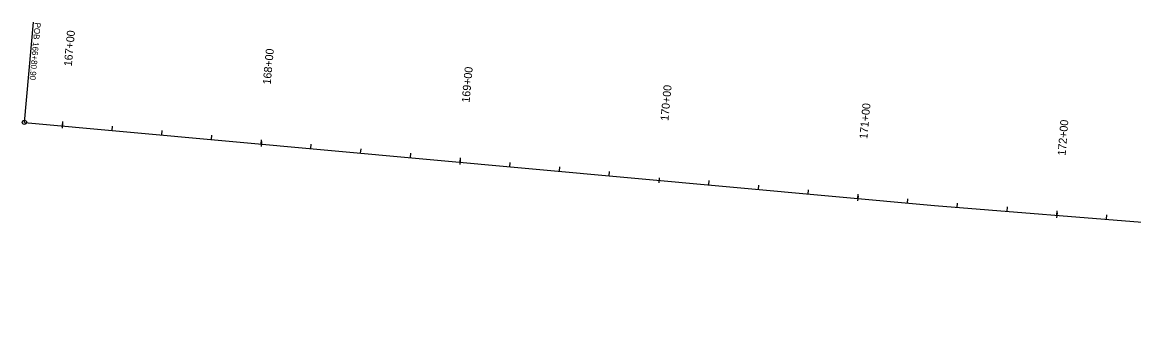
# Model space of a CAD drawing. Extents: x 20500393 to 20505339, y 7953466 to 7954298.
# Drawn here: x 20500393 to 20500950, y 7953909 to 7954061 of the extents above; entities that cross this region are included whole.
import ezdxf

# ---------------------------------------------------------------- set-up
doc = ezdxf.new("R2010")
doc.units = 0
for name, color, linetype in [('_CIVIL_CONSTRUCTION', 7, 'Continuous'), ('TextAlignment', 7, 'Continuous'), ('TextAlignmentLrg', 7, 'Continuous'), ('TextAlignmentSml', 7, 'Continuous')]:
    doc.layers.add(name, color=color, linetype=linetype)

msp = doc.modelspace()

# ---------------------------------------------------------------- linework, layer by layer
at = {"layer": '_CIVIL_CONSTRUCTION'}
for p, q in [((20500394.39, 7954010.65), (20500850.16, 7953968.94)), ((20500394.39, 7954010.65), (20500850.16, 7953968.94)), ((20500850.16, 7953968.94), (20501601.96, 7953909.2)), ((20500850.16, 7953968.94), (20501601.96, 7953909.2))]:
    msp.add_line(p, q, dxfattribs=at)
at = {"layer": 'TextAlignment'}
for p in [(20500394.39, 7954010.65), (20500398.98, 7954060.84)]:
    msp.add_line(p, (20500398.98, 7954060.84), dxfattribs=at)
msp.add_circle((20500394.39, 7954010.65), 1.07, dxfattribs=at)
at = {"layer": 'TextAlignmentLrg'}
for p, q in [((20500413.4, 7954008.91), (20500413.6, 7954011.09)), ((20500512.99, 7953999.8), (20500513.19, 7954001.97)), ((20500612.57, 7953990.69), (20500612.77, 7953992.86)), ((20500712.27, 7953982.79), (20500712.04, 7953980.35)), ((20500811.74, 7953972.46), (20500811.94, 7953974.64)), ((20500911.39, 7953964.08), (20500911.56, 7953966.26))]:
    msp.add_line(p, q, dxfattribs=at)
at = {"layer": 'TextAlignmentSml'}
for p, q in [((20500413.52, 7954010.13), (20500413.29, 7954007.69)), ((20500438.3, 7954006.63), (20500438.5, 7954008.81)), ((20500463.2, 7954004.36), (20500463.39, 7954006.53)), ((20500488.09, 7954002.08), (20500488.29, 7954004.25)), ((20500513.1, 7954001.02), (20500512.88, 7953998.58)), ((20500537.88, 7953997.52), (20500538.08, 7953999.7)), ((20500562.78, 7953995.24), (20500562.98, 7953997.42)), ((20500587.68, 7953992.96), (20500587.87, 7953995.14)), ((20500612.68, 7953991.91), (20500612.46, 7953989.47)), ((20500637.47, 7953988.41), (20500637.67, 7953990.58)), ((20500662.36, 7953986.13), (20500662.56, 7953988.3)), ((20500687.26, 7953983.85), (20500687.46, 7953986.03)), ((20500712.27, 7953982.79), (20500712.04, 7953980.35)), ((20500737.05, 7953979.29), (20500737.25, 7953981.47)), ((20500761.95, 7953977.02), (20500762.15, 7953979.19)), ((20500786.84, 7953974.74), (20500787.04, 7953976.91)), ((20500811.85, 7953973.68), (20500811.63, 7953971.24)), ((20500836.64, 7953970.18), (20500836.83, 7953972.36)), ((20500861.54, 7953968.04), (20500861.72, 7953970.22)), ((20500886.46, 7953966.06), (20500886.64, 7953968.24)), ((20500911.48, 7953965.3), (20500911.29, 7953962.86)), ((20500936.31, 7953962.1), (20500936.48, 7953964.28))]:
    msp.add_line(p, q, dxfattribs=at)

# ---------------------------------------------------------------- texts
at = {"layer": 'TextAlignment'}
for s, p in [('POB ', (20500399.63, 7954060.78)), ('166+80.90', (20500398.74, 7954050.97))]:
    msp.add_text(s, height=3, rotation=264.7714, dxfattribs=at).set_placement(p)
at = {"layer": 'TextAlignmentLrg'}
msp.add_text('170+00', height=4.008, rotation=84.7714, dxfattribs=at).set_placement((20500716.88, 7954011.27))
at = {"layer": 'TextAlignmentSml'}
for s, rotation, p in [('167+00', 84.7714, (20500418.13, 7954038.6)), ('168+00', 84.7714, (20500517.72, 7954029.49)), ('169+00', 84.7714, (20500617.3, 7954020.38)), ('170+00', 84.7714, (20500716.88, 7954011.27)), ('171+00', 84.7714, (20500816.47, 7954002.15)), ('172+00', 85.4564, (20500915.76, 7953993.83))]:
    msp.add_text(s, height=4.008, rotation=rotation, dxfattribs=at).set_placement(p)

doc.saveas('drawing.dxf')
